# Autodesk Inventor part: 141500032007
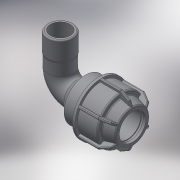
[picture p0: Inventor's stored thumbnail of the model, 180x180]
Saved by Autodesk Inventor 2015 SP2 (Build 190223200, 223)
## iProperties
Created: 2017-08
Part Number: 141500032007
Material: Generic
Description: L.14 90° ELBOW FEMALE ADAPTOR (SILVER) 32-3/4"
Document SubType Name: Modeling
Designer: KIM
Density: 1 g/cm^3
Appearance: Default
Author: KIM
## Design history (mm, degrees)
derived "141500.ipt"
feature "Solid1::141500.ipt"
feature "Solid2::141500.ipt"
tag "TaggingFeature1"
body "Solid1"
body "Solid2"
other parameters: "d1" = 32, "d2" = 56, "d4" = 15 deg, "d5" = 36.96, "d6" = 12.1968, "d10" = 61, "d16" = 32.64, "d17" = 2.8, "d22" = 51.2, "d24" = 2.8, "d25" = 54.9, "d26" = 45.75, "d27" = 2.8, "d28" = 135 deg, "d29" = 1.68, "d31" = 1.6, "d46" = 150 deg, "d49" = 3.05, "d50" = 0, "d58" = 0.96, "d61" = 360 deg, "d63" = 28.8, "d94" = 47, "d95" = 24.117, "d96" = 31.3521, "d97" = 18, "d98" = 19.2936, "d99" = 30.41154, "d100" = 135 deg, "d108" = 1.6, "d112" = 23.4, "d113" = 75, "d114" = 61.6, "d115" = 30.41154, "d116" = 45 deg, "d117" = 0, "d118" = 0, "d_" = 32, "G_" = 24.117, "E_" = 61, "A_" = 75, "l_" = 56, "l_2" = 18, "A_1" = 47
